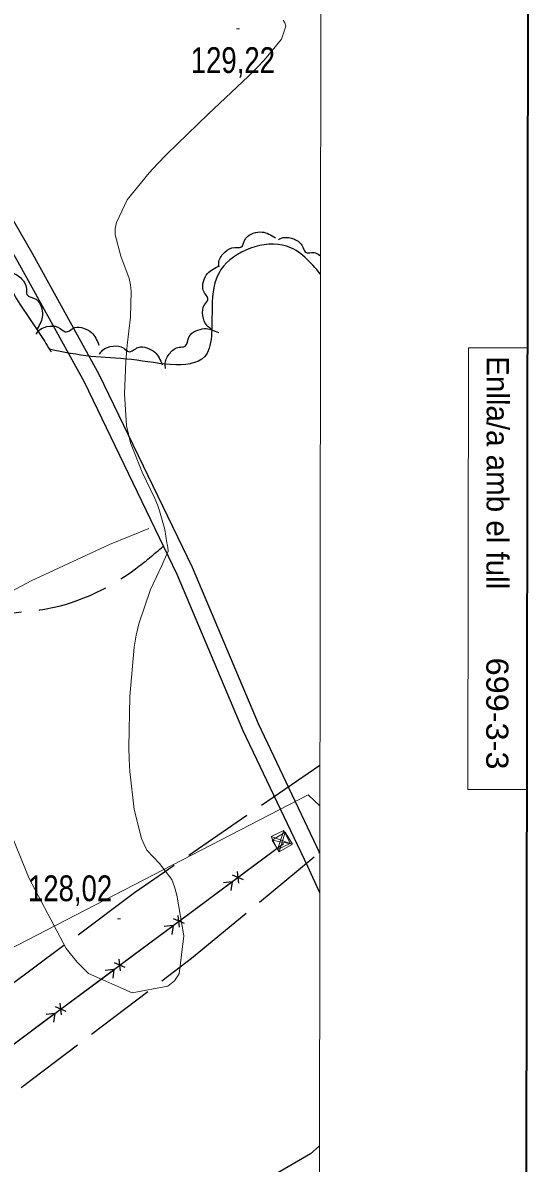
# Model space of a CAD drawing. Extents: x 487425 to 492029, y 4383576 to 4386788.
# Drawn here: x 491155.8 to 491328.9, y 4385077.8 to 4385465.2 of the extents above; entities that cross this region are included whole.
import ezdxf

# ---------------------------------------------------------------- set-up
doc = ezdxf.new("R2010")
doc.units = 0
doc.header["$LTSCALE"] = 4
doc.linetypes.add('DOTTED', pattern=[1.5, 0.3, -1.2])
doc.linetypes.add('LONG_DASHED', pattern=[7.5, 6, -1.5])
for name, color, linetype, lineweight in [('1', 7, 'Continuous', 13), ('2', 7, 'DOTTED', 13), ('24', 7, 'Continuous', 13), ('26', 7, 'LONG_DASHED', 25), ('27', 7, 'Continuous', 25), ('38', 7, 'Continuous', 25), ('43', 7, 'Continuous', 25), ('51', 7, 'Continuous', 13), ('7', 7, 'Continuous', 13), ('9', 7, 'Continuous', 13)]:
    doc.layers.add(name, color=color, linetype=linetype, lineweight=lineweight)

msp = doc.modelspace()

# ---------------------------------------------------------------- linework, layer by layer
at = {"layer": '1'}
msp.add_line((491326.97, 4385204.8), (491306.97, 4385204.82), dxfattribs=at)
at = {"layer": '1', "lineweight": 35}
msp.add_lwpolyline([(487611.46, 4386512.7), (491328.86, 4386507.3), (491325.3, 4384052.3), (487607.9, 4384057.7)], close=True, dxfattribs=at)
at = {"layer": '1'}
msp.add_lwpolyline([(487681.9, 4386441.2), (491258.2, 4386436), (491255.4, 4384123.8), (487678, 4384129)], close=True, dxfattribs=at)
msp.add_lwpolyline([(491327.19, 4385354.8), (491307.19, 4385354.82), (491306.97, 4385204.82)], dxfattribs=at)
at = {"layer": '24'}
msp.add_lwpolyline([(488954.49, 4384817.11), (489198.5, 4384851.16), (489357.39, 4384873.86), (489601.4, 4384907.91), (489794.34, 4384879.53), (490083.75, 4384822.79), (490248.31, 4384800.09), (490395.85, 4384817.11), (490526.37, 4384822.79), (490764.71, 4384947.63), (491088.16, 4385117.87), (491252.72, 4385202.99), (491256.7, 4385199.2)], dxfattribs=at)
at = {"layer": '26'}
for p, q in [((491256.66, 4385212.94), (491256.72, 4385212.98)), ((491256.41, 4385183.21), (491256.68, 4385183.42))]:
    msp.add_line(p, q, dxfattribs=at)
for points in [[(491256.66, 4385212.94), (491193.79, 4385169.68), (491122.92, 4385116.81), (491041.24, 4385059.54), (490958.82, 4385002.51), (490860.74, 4384924.98), (490760.29, 4384859), (490692.5, 4384806.79), (490609.37, 4384741.58), (490560.51, 4384697.87)], [(490600.09, 4384693.63), (490616.48, 4384709.55), (490676.36, 4384751.65), (490767.73, 4384815.34), (490869.55, 4384889.03), (490966.8, 4384964.62), (491046.3, 4385019.26), (491131.3, 4385085.44), (491213.14, 4385147.42), (491256.63, 4385183.39)]]:
    msp.add_lwpolyline(points, dxfattribs=at)
at = {"layer": '27'}
for points in [[(490552.62, 4384941.58), (490554.42, 4384943.67), (490554.9, 4384950.57), (490551.02, 4384958.75), (490549.23, 4384963.11), (490546.55, 4384969.04), (490546.27, 4384975.56), (490577.59, 4384991.51), (490608.31, 4385010.39), (490640.99, 4385029.26), (490675.61, 4385047.83), (490715.19, 4385070.58), (490756.65, 4385095.72), (490790.53, 4385116.54), (490822.22, 4385132.71), (490831.7, 4385141.3), (490834.32, 4385140.92), (490836.94, 4385139.04), (490838.42, 4385134.39), (490839.83, 4385127.26), (490841.17, 4385124.33), (490843.93, 4385120.95), (490854.88, 4385120.69), (490881, 4385131.56), (490910.74, 4385145.49), (490944, 4385160.61), (490977.26, 4385174.31), (491011.8, 4385191.9), (491038.91, 4385205.09), (491047.85, 4385210.16), (491048.16, 4385215.03), (491046.15, 4385220.51), (491027.8, 4385249.96), (491013.09, 4385271.3), (490994.07, 4385304.34), (490984.67, 4385319.67), (490979.29, 4385327.18), (490976.61, 4385330.57), (490974.75, 4385335.52), (490975.45, 4385343.54), (490977.85, 4385344.21), (490979.42, 4385344.13), (490980.47, 4385343.6), (490983.46, 4385341.64), (490988.77, 4385336.68), (490990.42, 4385334.95), (490993.78, 4385332.31), (491019.1, 4385348.81), (491045.47, 4385366.05), (491074.68, 4385380.36), (491106.91, 4385400.5), (491123.13, 4385410.28), (491127.87, 4385413.64), (491130.35, 4385415.43), (491144.45, 4385391.54), (491161.89, 4385359.02), (491165.47, 4385353.38)], [(491256.92, 4385379.85), (491245.41, 4385389.34), (491223.12, 4385381.37), (491219.99, 4385360.91), (491218.39, 4385352.97), (491192.74, 4385350.79), (491178.95, 4385351.87), (491164.91, 4385354.28)], [(491222.33, 4385382.35), (491222.44, 4385384.12), (491224.46, 4385387.33), (491227.8, 4385388.91), (491229.85, 4385388.98), (491231.59, 4385392.08), (491234.1, 4385393.7), (491237.1, 4385394.12), (491241.67, 4385392.2)], [(491242.64, 4385391.6), (491244.3, 4385392.22), (491248.05, 4385391.66), (491250.84, 4385389.24), (491251.73, 4385387.39), (491255.27, 4385387.05), (491256.93, 4385385.95)], [(491150.34, 4385380.28), (491152.12, 4385380.22), (491155.38, 4385378.28), (491157.04, 4385374.99), (491157.17, 4385372.94), (491160.31, 4385371.28), (491161.99, 4385368.81), (491162.49, 4385365.83), (491160.69, 4385361.21)], [(491219.83, 4385361.18), (491218.44, 4385362.27), (491216.95, 4385365.76), (491217.55, 4385369.41), (491218.66, 4385371.13), (491217.11, 4385374.33), (491217.21, 4385377.31), (491218.56, 4385380.02), (491222.74, 4385382.68)], [(491160.24, 4385359.42), (491161.38, 4385360.78), (491164.93, 4385362.13), (491168.54, 4385361.4), (491170.23, 4385360.23), (491173.48, 4385361.67), (491176.46, 4385361.46), (491179.11, 4385360.01), (491181.62, 4385355.73)], [(491204.31, 4385347.81), (491204.2, 4385349.59), (491205.81, 4385353.02), (491208.93, 4385355), (491210.95, 4385355.32), (491212.3, 4385358.61), (491214.59, 4385360.52), (491217.51, 4385361.32), (491222.28, 4385359.97)], [(491181.77, 4385352.62), (491182.91, 4385353.98), (491186.44, 4385355.36), (491190.07, 4385354.65), (491191.76, 4385353.49), (491195, 4385354.94), (491197.98, 4385354.75), (491200.64, 4385353.32), (491203.18, 4385349.05)]]:
    msp.add_spline(points, degree=3, dxfattribs=at)
at = {"layer": '38'}
for p, q in [((491256.63, 4385183.27), (491256.68, 4385183.16)), ((491256.61, 4385169.75), (491256.67, 4385169.63)), ((491256.56, 4385083.65), (491256.51, 4385083.6))]:
    msp.add_line(p, q, dxfattribs=at)
for points in [[(491113.03, 4385466.5), (491159.11, 4385386.77), (491181.67, 4385345.88), (491213.34, 4385280.28), (491235.71, 4385227.2), (491256.63, 4385183.27)], [(491108.09, 4385463.64), (491154.14, 4385383.96), (491176.6, 4385343.26), (491208.14, 4385277.93), (491230.5, 4385224.86), (491252.49, 4385178.68), (491256.61, 4385169.75)], [(491256.51, 4385083.6), (491253.58, 4385080.97), (491233.52, 4385069.4), (491207.31, 4385053.73), (491191.24, 4385046.65), (491172.24, 4385034.32), (491160.59, 4385025.73), (491159.08, 4385022.14), (491152.98, 4385011.06), (491148.38, 4385001.69), (491144.6, 4384991.28), (491131.52, 4384957.38)]]:
    msp.add_lwpolyline(points, dxfattribs=at)
at = {"layer": '38', "linetype": 'LONG_DASHED'}
msp.add_spline([(490856.41, 4385107.49), (490859.65, 4385110.18), (490867.38, 4385114.43), (490873.91, 4385115.53), (490887.03, 4385114.37), (490896.55, 4385115.32), (490924.27, 4385131.13), (490927.87, 4385133.82), (490941.1, 4385145.17), (490947.19, 4385149.8), (490963.04, 4385157.48), (490967.84, 4385158.06), (490984.27, 4385160.94), (490997.92, 4385161.95), (491003.62, 4385163.35), (491033.48, 4385171.21), (491039.72, 4385174.94), (491044.16, 4385180.85), (491046.74, 4385189.62), (491047.5, 4385195.54), (491053.9, 4385202.57), (491077.72, 4385221.09), (491118.14, 4385248.18), (491145.63, 4385263.7), (491161.54, 4385265.75), (491194.04, 4385279.67), (491203.47, 4385287.37)], degree=3, dxfattribs=at)
at = {"layer": '43', "lineweight": 13}
for p, q in [((491242.38, 4385184.33), (491244.48, 4385190.88)), ((491242.87, 4385183.56), (491244.97, 4385190.27)), ((491240.2, 4385188.79), (491246.66, 4385186.42)), ((491240.47, 4385187.59), (491247.37, 4385186.24))]:
    msp.add_line(p, q, dxfattribs=at)
at = {"layer": '43'}
for p, q in [((491230.83, 4385176.33), (491244.37, 4385186.39)), ((491230.76, 4385174.12), (491227.09, 4385175.7)), ((491229.15, 4385172.92), (491228.7, 4385176.89)), ((491210.76, 4385161.43), (491226.82, 4385173.35)), ((491226.91, 4385173.43), (491223.93, 4385173.08)), ((491226.91, 4385173.43), (491226.47, 4385170.46)), ((491210.69, 4385159.21), (491207.02, 4385160.8)), ((491209.08, 4385158.02), (491208.62, 4385161.99)), ((491190.69, 4385146.52), (491206.75, 4385158.45)), ((491206.84, 4385158.52), (491203.86, 4385158.18)), ((491206.84, 4385158.52), (491206.4, 4385155.56)), ((491190.61, 4385144.31), (491186.94, 4385145.9)), ((491189.01, 4385143.12), (491188.55, 4385147.09)), ((491170.62, 4385131.62), (491186.68, 4385143.54)), ((491186.77, 4385143.62), (491183.78, 4385143.27)), ((491186.77, 4385143.62), (491186.33, 4385140.65)), ((491168.94, 4385128.21), (491168.48, 4385132.18)), ((491150.55, 4385116.72), (491166.61, 4385128.64)), ((491166.69, 4385128.72), (491163.71, 4385128.37)), ((491166.69, 4385128.72), (491166.26, 4385125.75)), ((491170.54, 4385129.41), (491166.87, 4385130.99))]:
    msp.add_line(p, q, dxfattribs=at)
at = {"layer": '43', "lineweight": 13}
for points in [[(491242.38, 4385184.33), (491240.2, 4385188.79), (491244.48, 4385190.88), (491246.66, 4385186.42)], [(491242.87, 4385183.56), (491240.47, 4385187.59), (491244.97, 4385190.27), (491247.37, 4385186.24)]]:
    msp.add_lwpolyline(points, close=True, dxfattribs=at)
at = {"layer": '43'}
msp.add_lwpolyline([(489809.89, 4384125.9), (490053.43, 4384305.98), (490295.56, 4384486.1), (490534.15, 4384662.33), (490743.89, 4384815.26), (490986.91, 4384995.23), (491244.37, 4385186.39)], dxfattribs=at)
at = {"layer": '51'}
msp.add_lwpolyline([(490820.72, 4385163.37), (490845.2, 4385119.74), (490956.54, 4385166.65), (491000.39, 4385185.71), (491050.47, 4385208.05), (491111.7, 4385250.6), (491158.64, 4385275.65), (491185.22, 4385287.95), (491198.66, 4385293.38)], dxfattribs=at)
at = {"layer": '7'}
for p, q in [((491228.44, 4385463.19), (491229.44, 4385463.19)), ((491188.01, 4385160.85), (491189.01, 4385160.85))]:
    msp.add_line(p, q, dxfattribs=at)
at = {"layer": '9'}
for points in [[(491208.94, 4385142.15), (491210.55, 4385155.11), (491208.18, 4385168.85), (491207.32, 4385171.71), (491206.37, 4385174.17), (491202.19, 4385179.66), (491197.98, 4385184.19), (491197.01, 4385186.05), (491196.12, 4385188.17), (491193.61, 4385197.99), (491192.19, 4385210.87), (491191.98, 4385214.92), (491191.86, 4385219.18), (491192.1, 4385236.3), (491193.65, 4385253.13), (491194.36, 4385257.21), (491195.18, 4385261.04), (491199.16, 4385272.75), (491202.98, 4385280.87), (491203.71, 4385282.43), (491204.3, 4385283.7), (491205.22, 4385285.77), (491205.04, 4385286.96), (491204.92, 4385287.66), (491204.77, 4385288.53), (491204.02, 4385293.03), (491202.28, 4385299.4), (491201.51, 4385301.45), (491200.62, 4385303.63), (491196.38, 4385312.53), (491192.38, 4385322.54), (491191.65, 4385325.41), (491191.07, 4385328.34), (491190.33, 4385339.27), (491190.82, 4385350.08), (491191.02, 4385352.92), (491191.25, 4385355.7), (491192.33, 4385365.19), (491192.6, 4385373.89), (491192.33, 4385376.17), (491191.9, 4385378.39), (491189.11, 4385385.92), (491187.13, 4385393.21), (491187.22, 4385395.28), (491187.58, 4385397.36), (491191.21, 4385405.06), (491198.74, 4385414.28), (491201.57, 4385417.32), (491204.73, 4385420.58), (491218.81, 4385434.11), (491232.49, 4385447.1), (491235.38, 4385450.01), (491237.89, 4385452.62), (491243.74, 4385459.58), (491245.12, 4385464.08), (491244.81, 4385465.15), (491244.21, 4385466.13)], [(491148.05, 4385198.77), (491158.01, 4385174.55), (491170.54, 4385150.74), (491174.27, 4385146.1), (491178.12, 4385142.31), (491192.95, 4385135.65), (491205.12, 4385137.93), (491207.29, 4385139.78), (491208.94, 4385142.15)]]:
    msp.add_lwpolyline(points, dxfattribs=at)

# ---------------------------------------------------------------- texts
at = {"layer": '2'}
msp.add_text('Enlla/a amb el full', height=7.5, rotation=269.917, dxfattribs=at).set_placement((491313.43, 4385351.94))
at = {"layer": '2', "width": 1.1}
msp.add_text('699-3-3', height=7.5, rotation=269.917, dxfattribs=at).set_placement((491313.29, 4385249.57))
at = {"layer": '7', "width": 0.8}
for s, p in [('129,22', (491212.85, 4385448.15)), ('128,02', (491157.54, 4385166.83))]:
    msp.add_text(s, height=8.75, dxfattribs=at).set_placement(p)

doc.saveas('drawing.dxf')
